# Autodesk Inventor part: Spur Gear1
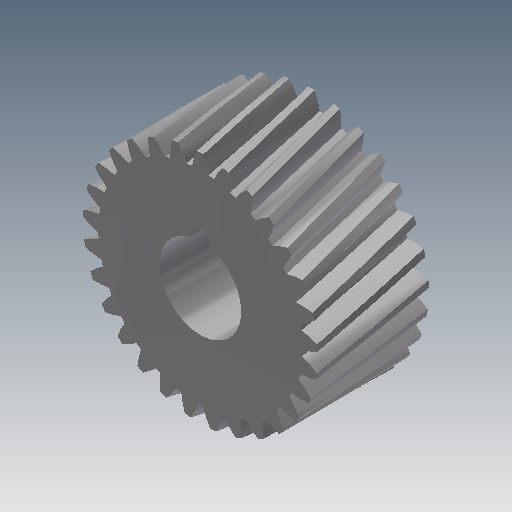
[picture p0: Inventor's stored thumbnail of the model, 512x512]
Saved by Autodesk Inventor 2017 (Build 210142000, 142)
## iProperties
Created: 2019-03
Part Number: Spur Gear1
Material: Steel
Document SubType Name: Modeling
Designer: user
Categories: <?xml version="1.0" encoding="UTF-16"?> <MemberInstance><Categories><FamilyTemplate><FamilyTemplateParameter ValueType="xs:double" Id="1" ObjectReferenceKey="da
Density: 7.85 g/cm^3
Appearance: Steel
Mass: 560.425 g
Surface Area: 176.325 cm^2
Volume: 71.3917 cm^3
CustomPartVersion: 1
Author: user
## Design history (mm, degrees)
sketch "Sketch1"
  geometry: C1 r 31.647 at (0, 0)
  constraints: 1 centre point
  dimensions: "d0" = 63.29459 diameter of C1 (= da_da)
extrude "Extrusion1" new body sketch "Sketch1" distance "d1" = 30 (= da_b); taper "d2" = 0 deg
workplane "Work Plane2"
sketch "Sketch2"
  geometry: C1 r 31.647 at (0, 0) reference; C2 r 28.663 at (0, 0)
  constraints: 1 centre point, 1 coincident
  dimensions: "d3" = 57.32558 diameter of C2 (= da_dw)
feature "Pitch Diameter" sketch "Sketch2" dims "d4" = 10, "d5" = 0
workplane "Work Plane8"
workplane "Work Plane9"
feature "Spur Gear" dims "da_b" = 30, "da_d" = 59.29575, "da_aw" = 85, "da_da" = 63.29459, "da_df" = 55.09575, "da_dw" = 57.32558, angle "da_beta" = 12 deg, "da_lefttooth" = 10, "da_righttooth" = 0
sketch "Sketch3"
  geometry: L1 (2.654, 10.675)-(2.654, 13.789); L2 (2.654, 13.789)-(-2.654, 13.789); L3 (-2.654, 13.789)-(-2.654, 10.675); A1 r 11 centre (0, 0) between (-2.654, 10.675) and (2.654, 10.675); 2 further points
  constraints: 6 end point, 2 point on circle, 1 centre point, 1 coincident, 1 midpoint, 1 parallel, 1 vertical alignment
  dimensions: "d49" = 22 diameter of A1
extrude "Extrusion2" cut sketch "Sketch3" stored distance "d50" = 10; taper "d51" = 0 deg
body "Solid1"
body "Srf1"
other parameters: "d16" = 85 (= da_aw), "d17" = 0, "d34" = 1.08331 (computed from da_z), "d39" = 0, "d41" = 0, "d43" = 85 (= da_aw), "d46" = 85 (= da_aw), "d47" = 0, "d48" = 0
